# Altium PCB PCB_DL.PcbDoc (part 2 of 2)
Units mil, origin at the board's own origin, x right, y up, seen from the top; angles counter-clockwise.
Board outline 3150 x 3254.21 mil, 2 copper layers (Top Layer, Bottom Layer); 110 components, 96 nets, 420 pads, 120 vias.
Unrouted connection lines stored in the file: 79.
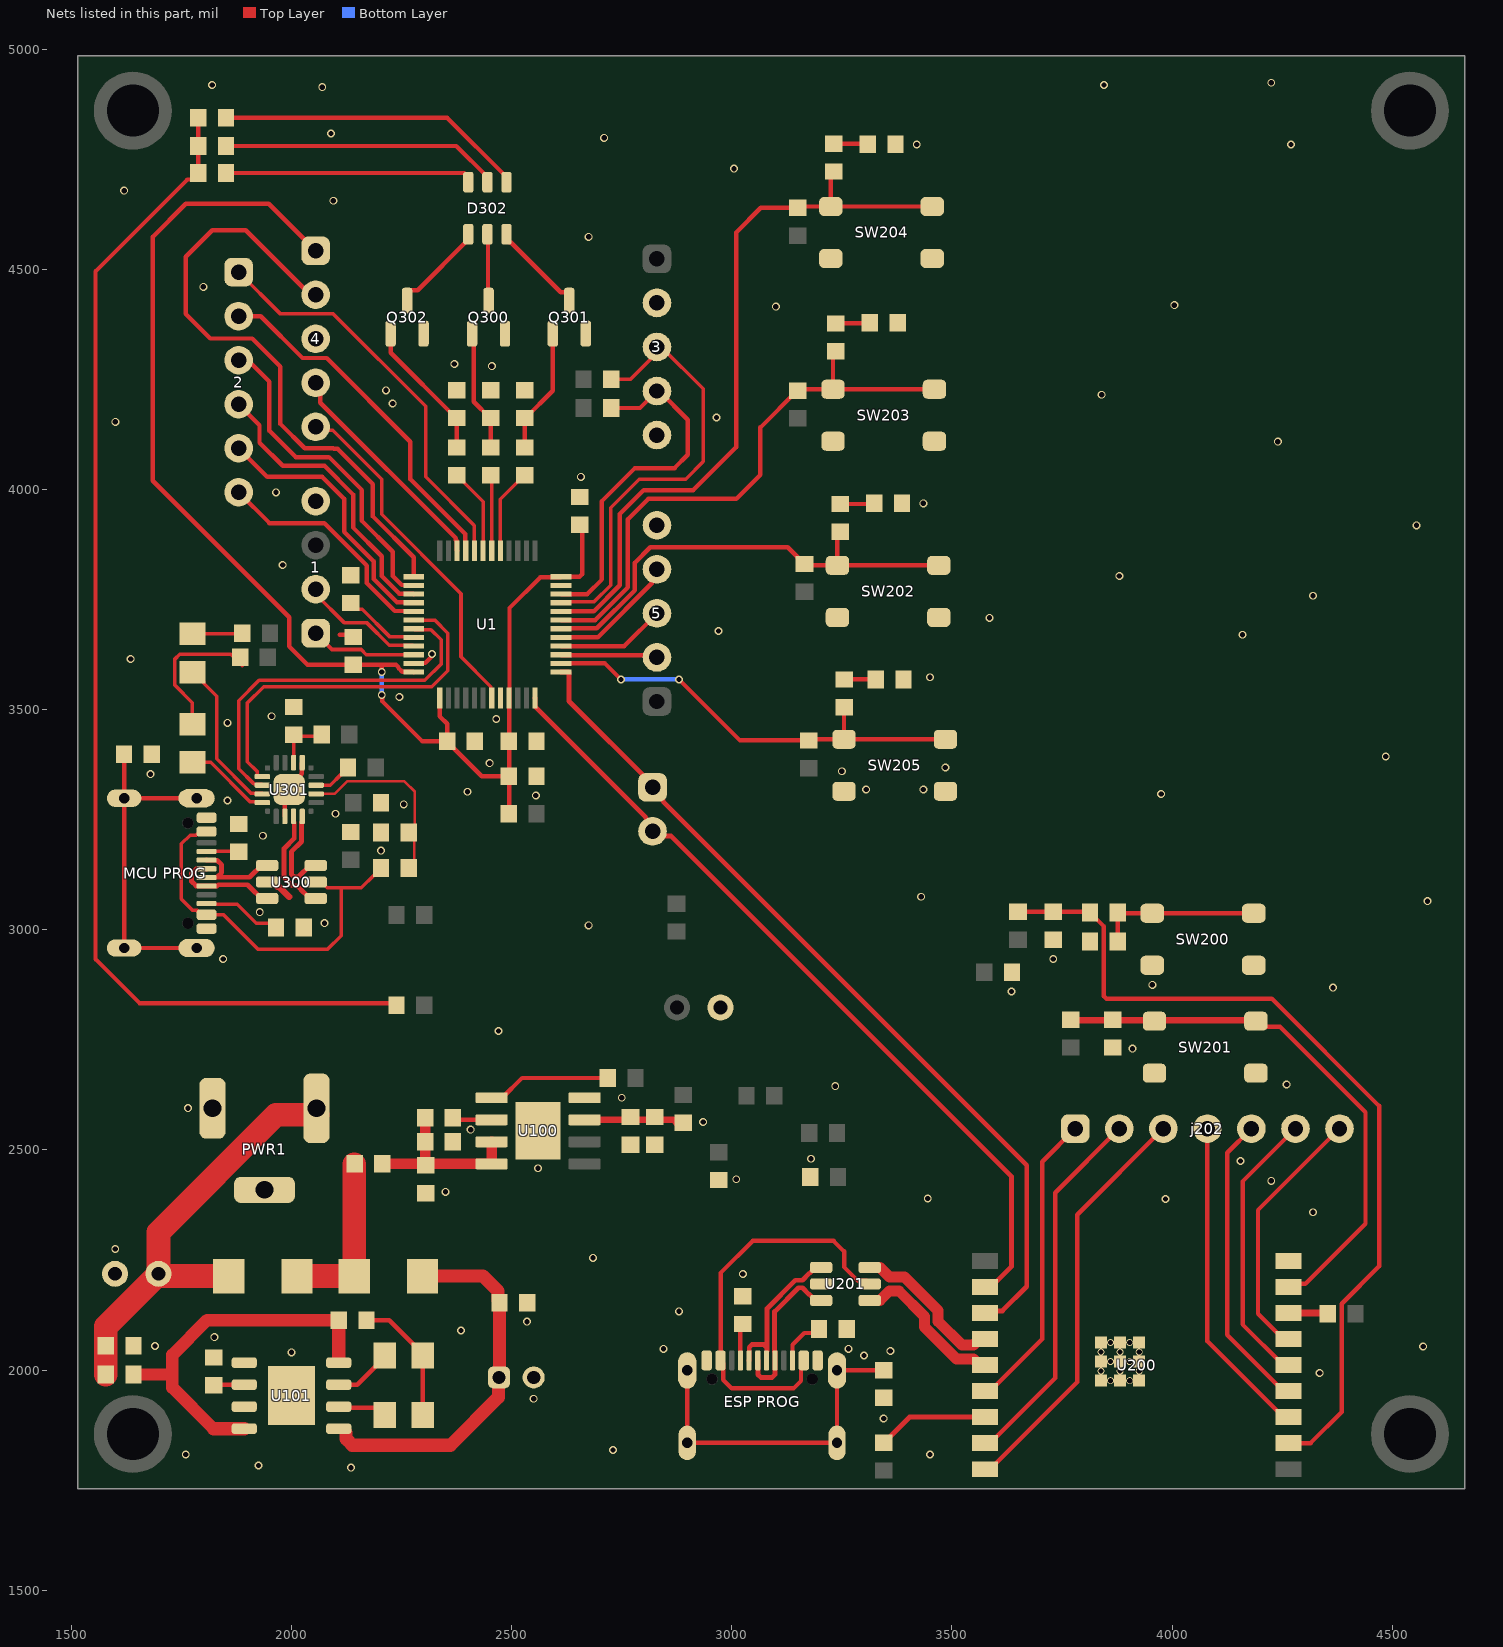
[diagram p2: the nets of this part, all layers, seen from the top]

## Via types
v1: diameter 18, hole 12, Top Layer to Bottom Layer, tented both sides, 120 vias

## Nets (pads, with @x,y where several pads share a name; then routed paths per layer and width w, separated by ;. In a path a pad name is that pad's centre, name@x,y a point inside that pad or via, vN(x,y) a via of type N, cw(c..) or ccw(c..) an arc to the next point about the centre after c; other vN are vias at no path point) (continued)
3V3_LED: FB302.2 R311.2 R312.2 R313.2 | length 2749.3
  Top Layer w10: R311.2@1788.66,4718.51 R311.2@1788.66,4728.66 ; R313.2@1788.66,4844.3 R312.2@1788.66,4779.86 R311.2@1788.66,4728.66 ; FB302.2@2238.57,2833.5 1655.07,2833.5 1555.07,2933.5 1555.07,4495.07 1763.73,4703.73 1775.16,4703.73 1788.66,4717.23 R311.2@1788.66,4728.66
3V3_MCU: 4.1 C1.1 C2.1 C3.1 C4.1 C5.1 FB1.2 U1.1 U1.9 U1.24 U1.48 | length 3133.8
  Top Layer w10: 4.1@2055,4542 1948.5,4648.5 1760.07,4648.5 1685.07,4573.5 1685.07,4019.93 1995.07,3709.93 1995.07,3643.5 2036.57,3602 C4.1@2140.07,3602 2205.07,3602 ; v1(2205.07,3533) 2206.6,3531.47 2206.6,3518.69 2296.78,3428.5 C3.1@2353.57,3428.5 2353.57,3467.7 2336.8,3484.47 U1.1@2336.8,3526.18 ; v1(2205.07,3585.5) 2205.07,3602 ; U1.48@2277.75,3585.23 2276.75,3586.23 2251.37,3586.23 2243.25,3594.36 2243.25,3596.14 2237.39,3602 2205.07,3602 ; C3.1@2353.57,3427 2432.07,3348.5 C1.1@2493.57,3348.5 ; FB1.2@2494.28,3264.21 U1.9@2494.28,3526.18 2495.28,3527.18 2495.28,3730.69 2565.36,3800.77 2611.39,3800.77 U1.24@2612.39,3801.77 2654.21,3801.77 2660.07,3807.63 2660.07,3907 C5.1@2650.07,3917
  Bottom Layer w10: v1(2205.07,3533) v1(2205.07,3585.5)
5V: C100.1 C106.1 D103.2 FB101.1 PWR1.1 | length 1000.6
  Top Layer w54: FB101.1@1578.5,1990.17 1578.5,2099.36 C100.1@1697.97,2218.82 ; D103.2@1847.71,2213.7 1697,2213.7 1697,2217.86 C100.1@1697.97,2218.82 ; PWR1.1@2059.47,2580 1965,2580 1697.97,2312.97 C100.1@1697.97,2218.82
BTN_1: C207.1 R208.1 SW202.2 U1.18 | length 1063.5
  Top Layer w10: U1.18@2612.39,3683.66 2613.39,3684.66 2693.6,3684.66 2780.07,3771.13 2780.07,3833.5 2815.07,3868.5 3127.28,3868.5 3150.07,3845.71 3150.07,3844.21 3163.57,3830.71 R208.1@3165.07,3830.71 ; R208.1@3168.22,3827.56 SW202.2@3239.91,3827.56 ; C207.1@3246.49,3904 3239.91,3897.43 SW202.2@3239.91,3827.56 ; SW202.2@3470.23,3827.56 SW202.2@3239.91,3827.56
BTN_2: C208.1 R209.1 SW203.2 U1.19 | length 1303.2
  Top Layer w10: U1.19@2612.39,3703.34 2689.66,3703.34 2764.07,3777.76 2764.07,3932.5 2810.07,3978.5 3010.07,3978.5 3065.07,4033.5 3065.07,4140.9 3148.57,4224.4 R209.1@3150.07,4224.4 ; R209.1@3153.22,4227.56 SW203.2@3229.91,4227.56 ; C208.1@3236.49,4314 3229.91,4307.43 SW203.2@3229.91,4227.56 ; SW203.2@3460.23,4227.56 SW203.2@3229.91,4227.56
BTN_3: C209.1 R210.1 SW204.2 U1.20 | length 1681.8
  Top Layer w10: U1.20@2612.39,3723.03 2686.71,3723.03 2745.81,3782.12 2745.81,3944.24 2800.07,3998.5 2912.34,3998.5 3010.07,4096.23 3010.07,4583.5 3065.97,4639.4 R210.1@3150.07,4639.4 ; R210.1@3153.22,4642.56 SW204.2@3224.91,4642.56 ; C209.1@3231.49,4722 3224.91,4715.43 SW204.2@3224.91,4642.56 ; SW204.2@3455.23,4642.56 SW204.2@3224.91,4642.56
BTN_4: C210.1 R211.1 SW205.2 U1.14 | length 1016
  Top Layer w10: U1.14@2612.39,3604.92 2711.9,3604.92 v1(2748.58,3568.24) ; v1(2880.07,3568.5) 3018.57,3430 R211.1@3175.07,3430 ; R211.1@3177.62,3432.56 SW205.2@3254.91,3432.56 ; C210.1@3255.07,3505.5 3254.91,3505.34 SW205.2@3254.91,3432.56 ; SW205.2@3485.23,3432.56 SW205.2@3254.91,3432.56
  Bottom Layer w10: v1(2748.58,3568.24) 2748.84,3568.5 v1(2880.07,3568.5)
D2_C_N: "ESP PROG.A7" "ESP PROG.B7" U201.1 | length 353.6
  Top Layer w11: 3039.4,2021.98 3039.81,2022.38 3039.81,2052.06 3046.25,2058.5 3071.93,2058.5 3078.37,2052.06 ; 3079.18,2022.38 3079.18,2042.56 3080.12,2043.5 3080.12,2139.97 3144.41,2204.26 3160.56,2204.26 3176.36,2220.06 3176.58,2220.06 3189.68,2233.16 U201.1@3202.96,2233.16
D2_C_P: "ESP PROG.A6" "ESP PROG.B6" U201.3 | length 360.1
  Top Layer w11: 3059.09,2021.98 3059.49,2021.57 3059.49,1989.94 3065.94,1983.5 3091.61,1983.5 3098.05,1989.94 3098.05,2021.57 3098.46,2021.98 3098.05,2022.38 3098.05,2041.42 3097.12,2042.36 3097.12,2132.93 3151.45,2187.26 3160.56,2187.26 3176.36,2171.47 3176.58,2171.47 3189.68,2158.36 U201.3@3202.96,2158.36
D_C_N: "MCU PROG.A7" "MCU PROG.B7" U300.1 | length 220
  Top Layer w11: 1807.23,3118.82 1807.63,3119.22 1831.02,3119.22 ; 1807.23,3158.19 1807.63,3157.78 1831.02,3157.78 1841.37,3147.44 1841.37,3129.56 1831.02,3119.22 ; U300.1@1944.95,3145.9 1931.67,3145.9 1918.56,3132.8 1918.34,3132.8 1904.77,3119.22 1831.02,3119.22
D_C_P: "MCU PROG.A6" "MCU PROG.B6" U300.3 | length 247
  Top Layer w11: 1807.23,3138.5 1806.82,3138.09 1783.43,3138.09 1773.09,3127.75 1773.09,3109.88 1783.43,3099.54 1806.82,3099.54 1807.23,3099.13 1807.63,3099.54 1831.02,3099.54 1833.71,3102.22 1900.33,3102.22 1918.34,3084.2 1918.56,3084.2 1931.67,3071.1 U300.3@1944.95,3071.1
DATA_ESP_N: U200.13 U201.6 | length 354.9
  Top Layer w25: U201.6@3313.2,2233.16 3313.49,2232.87 3336.9,2232.87 3358.5,2211.27 3392.05,2211.27 3468.33,2134.99 3468.33,2111 3522.69,2056.64 3549.23,2056.64 3563.26,2070.67 U200.13@3575.07,2070.67
DATA_ESP_P: U200.14 U201.4 | length 354.9
  Top Layer w25: U201.4@3313.2,2158.36 3313.49,2158.66 3336.89,2158.66 3358.5,2180.27 3379.21,2180.27 3437.33,2122.15 3437.33,2098.16 3509.84,2025.64 3549.23,2025.64 3563.26,2011.61 U200.14@3575.07,2011.61
DATA_MCU_N: U300.6 U301.5 | length 209.9
  Top Layer w11: U301.5@2024.6,3257.48 2024.6,3245.67 2023.25,3244.32 2023.25,3200.51 2000.07,3177.32 2000.07,3126.29 2006.51,3119.85 2015.62,3119.85 2028.58,3132.8 2028.81,3132.8 2041.91,3145.9 U300.6@2055.19,3145.9
DATA_MCU_P: U300.4 U301.4 | length 240.4
  Top Layer w11: U301.4@2004.91,3257.48 2004.91,3245.67 2006.25,3244.32 2006.25,3207.55 1983.07,3184.36 1983.07,3119.25 2002.31,3100 2012.79,3100 2028.58,3084.21 2028.79,3084.21 2041.91,3071.1 U300.4@2055.19,3071.1
ESP_BOOT: C204.1 R203.1 SW201.2 U200.8 | length 1243.9
  Top Layer w10: SW201.2@4190.23,2792.56 4202.78,2780 4245,2780 4439.12,2585.88 4439.12,2332.56 4302.71,2196.15 4271.42,2196.15 U200.8@4264.04,2188.78
  Top Layer w15: R203.1@3770.07,2795.71 3771.65,2794.13 3865.07,2794.13 3959.91,2794.13 4188.65,2794.13 SW201.2@4190.23,2792.56
GND: 1.4 3.2 3.5 4.3 5.5 "ESP PROG.A1/B12" "ESP PROG.B1/A12" "MCU PROG.A1/B12" "MCU PROG.B1/A12" C1.2 C2.2 C3.2 C4.2 C5.2 C100.2 C101.2 C102.2 C103.2 C104.2 C105.2 C106.2 C200.2 C201.2 C202.2 C203.2 C204.2 C300.2 C301.2 FB200.1 FB301.1 PWR1.2 PWR1.3 Q300.2 Q301.2 Q302.2 R1.1 R103.2 R104.1 R106.2 R212.1 R213.1 R214.1 R215.1 R216.1 R217.1 R303.1 R304.1 R307.1 R308.1 R310.1 R316.1 R317.1 SW200.1 SW201.1 SW202.1 SW203.1 SW204.1 SW205.1 U1.8 U1.23 U1.47 U100.8 U100.9 U101.1 U101.3 U101.9 U200.9 U200.19 U201.2 U300.2 U301.3 U301.12 U301.21 X101.2 | length 287.9
  Top Layer w10: U301.3@1985.23,3257.48 1985.23,3308.66 U301.21@1995.07,3318.5 1995.07,3325.38 2023.69,3354 2023.69,3378.62 U301.12@2024.6,3379.52 ; 2110.07,3670 2135.07,3670 C4.2@2140.07,3665 ; U1.47@2277.75,3604.92 2278.75,3605.92 2304.12,3605.92 2317.67,3619.48 2317.67,3624.71 v1(2319.21,3626.24)
  Top Layer w15: U300.2@1944.95,3108.5 1957.75,3108.5 1968.85,3097.39 1972.39,3097.39 1995.07,3074.71
  other v1: 2135.07,1778.5 1925.07,1783.5 1760.07,1808.5 3450.07,1808.5 2730.07,1818.5 3344.87,1890.12 2550,1935 4335.07,1993.5 3300.07,2033.5 2000.07,2040.43 3360.07,2043.5 2845.07,2048.5 3265.07,2048.5 4570.07,2053.5 1690,2055 1825,2075 2385,2090 2535,2110 2880.07,2133.5 3025.07,2218.5 2685,2255 1600,2275 4320.07,2358.5 3985.07,2388.5 3445,2390 2350,2405 4225,2430 3010.07,2433.5 2560.07,2458.5 4155,2475 3180,2480 2406.93,2546.18 2935.07,2563.5 1765,2595 2750.07,2618.5 3235,2645 4260.07,2648.5 3910,2730 2470,2770 3635,2860 4365.07,2868.5 3955,2875 1845.07,2933.5 3730.07,2933.5 2675,3010 2075,3015 1928.09,3040.01 4580,3065 3430,3075 2203.51,3179.64 1935.07,3213.5 2100.07,3263.5 2255,3285 1855.07,3293.5 2555,3305 3975.07,3308.5 2400.07,3313.5 3305.07,3318.5 3435.07,3318.5 1680.07,3353.5 3250,3360 3485.07,3368.5 2450.07,3378.5 4485.07,3393.5 1855,3470 2465.07,3478.5 1955,3485 2245.07,3528.5 3450.07,3573.5 1635,3615 4160,3670 2970.07,3678.5 3585.07,3708.5 4320.07,3758.5 3880.07,3803.5 1980.07,3828.5 4555.07,3918.5 3435.07,3968.5 1965.07,3993.5 2657.11,4028.5 4240.07,4108.5 1600.07,4153.5 2965.07,4163.5 2230,4195 3840,4215 2215,4225 2455,4280 2370,4285 3100,4415 4005.07,4418.5 1800,4460 2675.07,4573.5 2095.07,4655.51 1620.07,4678.5 3005.07,4728.5 3420.07,4783.5 4270.07,4783.5 2710.07,4798.5 2090.07,4808.5 2070.07,4913.5 1820.07,4918.5 3845.07,4918.5 4225.07,4923.5
I/O_0: j202.3 U200.18 | length 947.8
  Top Layer w10: U200.18@3575.07,1775.39 3586.88,1775.39 3784.57,1973.08 3784.57,2353 j202.3@3980.07,2548.5
I/O_1: j202.2 U200.17 | length 847.3
  Top Layer w10: U200.17@3575.07,1834.44 3586.88,1834.44 3734.57,1982.14 3734.57,2403 j202.2@3880.07,2548.5
I/O_3: j202.1 U200.15 | length 687.8
  Top Layer w10: U200.15@3575.07,1952.56 3586.88,1952.56 3705,2070.68 3705,2473.43 j202.1@3780.07,2548.5
I/O_4: j202.4 U200.3 | length 738.1
  Top Layer w10: j202.4@4080.07,2548.5 4080.07,2065.67 4252.23,1893.5 U200.3@4264.04,1893.5
I/O_5: j202.5 U200.4 | length 683.3
  Top Layer w10: j202.5@4180.07,2548.5 4125,2493.43 4125,2080 4239.52,1965.48 4239.52,1965.27 4252.23,1952.56 U200.4@4264.04,1952.56
I/O_6: j202.6 U200.5 | length 636.6
  Top Layer w10: U200.5@4264.04,2011.61 4252.23,2011.61 4160,2103.84 4160,2428.43 j202.6@4280.07,2548.5
I/O_7: j202.7 U200.6 | length 590
  Top Layer w10: U200.6@4264.04,2070.67 4252.23,2070.67 4195.07,2127.83 4195.07,2363.5 j202.7@4380.07,2548.5
LB: D302.1 Q302.3 | length 218.6
  Top Layer w10: Q302.3@2262.67,4428.5 2262.67,4445.73 2269.41,4452.47 2286.6,4452.47 2401.76,4567.63 D302.1@2401.76,4579.44
LED1_B: R315.1 U1.31 | length 197
  Top Layer w8: R315.1@2375.07,4032 2376.57,4032 2391.07,4017.5 2391.07,4016 2435.23,3971.84 U1.31@2435.23,3860.82
LED1_G: R309.1 U1.30 | length 171.2
  Top Layer w8: U1.30@2454.91,3860.82 2454.91,4031.84 R309.1@2455.07,4032
LED1_R: R314.1 U1.29 | length 195
  Top Layer w8: U1.29@2474.6,3860.82 2474.6,3978.03 2528.57,4032 R314.1@2530.07,4032
LG: D302.2 Q300.3 | length 152
  Top Layer w10: D302.2@2445.07,4579.44 2446.37,4578.15 2446.37,4429.8 Q300.3@2447.67,4428.5
LR: D302.3 Q301.3 | length 219.3
  Top Layer w10: D302.3@2488.38,4579.44 2488.38,4568.12 2495.12,4561.38 2498.17,4561.38 2611.51,4448.05 2624.31,4448.05 2631.05,4441.3 Q301.3@2631.05,4428.5
NetC101_1: C101.1 C102.1 FB100.2 R101.2 U100.3 U100.4 | length 407.9
  Top Layer w10: C101.1@2303.57,2470 C101.1@2305.07,2468.5 ; C102.1@2303.57,2517 C102.1@2303.57,2518.5 ; 2366.57,2468.5 2370.07,2465 2373.57,2468.5
  Top Layer w24: FB100.2@2206.57,2468.5 2305.07,2468.5 2366.57,2468.5 ; C101.1@2303.57,2470 C102.1@2303.57,2518.5 R101.2@2303.57,2573.5 ; 2373.57,2468.5 U100.4@2454.46,2468.5 U100.3@2454.46,2518.5
NetC200_1: C200.1 R200.2 R201.2 U200.2 | length 1975.6
  Top Layer w10: R200.2@3650.07,3040.71 C200.1@3730.07,3040.71 3812.07,3040.71 R201.2@3813.57,3039.21 3845.07,3007.71 3845.07,2849.36 3850.93,2843.5 4226.5,2843.5 4470,2600 4470,2235.99 4385,2150.99 4385,1905 4314.44,1834.44 U200.2@4264.04,1834.44
NetC201_1: C201.1 R201.1 SW200.2 | length 375.1
  Top Layer w10: C201.1@3876.57,2973.5 R201.1@3876.57,3039.21 3878.22,3037.56 SW200.2@3954.91,3037.56 SW200.2@4185.23,3037.56
NetC207_2: C207.2 R214.2 | length 77.7
  Top Layer w10: C207.2@3246.49,3967 3322.07,3967 R214.2@3323.57,3968.5
NetC208_2: C208.2 R215.2 | length 77.7
  Top Layer w10: C208.2@3236.49,4377 3312.07,4377 R215.2@3313.57,4378.5
NetC209_2: C209.2 R216.2 | length 77.7
  Top Layer w10: C209.2@3231.49,4785 3307.07,4785 R216.2@3308.57,4783.5
NetC210_2: C210.2 R217.2 | length 72
  Top Layer w10: C210.2@3255.07,3568.5 R217.2@3327.07,3568.5
NetD101_1: D101.1 D102.1 R105.2 | length 298.5
  Top Layer w10: R105.2@2170.35,2113.5 2222.31,2113.5 2298.38,2037.44 D102.1@2298.38,2033.5 D101.1@2298.38,1898.5
NetD101_2: D101.2 U101.6 | length 112.1
  Top Layer w10: U101.6@2107.36,1917.01 2109.62,1914.73 2195.53,1914.73 D101.2@2211.76,1898.5
NetD102_2: D102.2 U101.7 | length 134.3
  Top Layer w10: U101.7@2107.36,1967.01 2149.2,1967 2211.76,2029.56 D102.2@2211.76,2033.5
NetD300_1: D300.1 R300.1 | length 334.2
  Top Layer w8: D300.1@1775.07,3466.81 1775.07,3515.93 1735.54,3555.46 1735.54,3614.93 1746.43,3625.81 1862.75,3625.81 1873.32,3615.25 R300.1@1888.57,3600 ; R300.1@1872.57,3614.5 R300.1@1874.07,3614.5
NetD300_2: D300.2 U301.20 | length 196.8
  Top Layer w8: D300.2@1775.07,3380.19 1816.6,3380.19 1905.91,3290.88 1932.14,3290.88 U301.20@1934.04,3288.97
NetD301_1: D301.1 R301.1 | length 115.7
  Top Layer w8: D301.1@1775.07,3671.81 1886.88,3671.81 R301.1@1888.57,3673.5 R301.1@1888.57,3672
NetD301_2: D301.2 U301.19 | length 358.8
  Top Layer w8: D301.2@1775.07,3585.19 1779.01,3585.19 1800.6,3563.6 1800.6,3559.67 1830.07,3530.19 1830.07,3388.5 1908.01,3310.56 1932.14,3310.56 U301.19@1934.04,3308.66
NetD302_4: D302.4 R313.1 | length 704.4
  Top Layer w10: R313.1@1851.66,4844.3 2353.44,4844.3 2488.38,4709.37 D302.4@2488.38,4697.56
NetD302_5: D302.5 R312.1 | length 634.4
  Top Layer w10: R312.1@1851.66,4779.86 2374.58,4779.86 2445.07,4709.37 D302.5@2445.07,4697.56
NetD302_6: D302.6 R311.1 | length 565.4
  Top Layer w10: R311.1@1851.66,4718.51 2392.12,4718.51 2401.76,4708.88 D302.6@2401.76,4697.56
"NetESP PROG_0": "ESP PROG.0" FB200.2 | length 775.6
  Top Layer w10: 2898.85,1999.34 2898.85,1834.77 3239.01,1834.77 3239.01,1999.34 3344.41,1999.34 FB200.2@3345.07,2000
"NetESP PROG_A5": "ESP PROG.A5" R213.2 | length 91.8
  Top Layer w10: R213.2@3015.7,2108.63 3023.18,2108.63 R213.2@3023.81,2108 ; R213.2@3018.81,2105 3018.81,2022.88 3019.72,2021.98
"NetESP PROG_B5": "ESP PROG.B5" R212.2 | length 104.8
  Top Layer w10: 3137.83,2021.98 3137.83,2057.76 3164.43,2084.36 3182.93,2084.36 R212.2@3192.07,2093.5
NetFB101_2: FB101.2 R105.1 U101.4 U101.8 | length 867
  Top Layer w28: FB101.2@1641.5,1990.17 1729.61,1990.17 ; 1823,1867 1729.61,1960.39 1729.61,1990.17 ; R105.1@2107.35,2113.5 1808.5,2113.5 1729.61,2034.61 1729.61,1990.17
  Top Layer w30: 1823,1867 U101.4@1892.8,1867.01 ; U101.8@2107.35,2021.11 R105.1@2107.35,2113.5
NetFB301_2: "MCU PROG.0" FB301.2 | length 769.2
  Top Layer w10: FB301.2@1620.02,3398.66 1620.02,3298.74 ; 1784.59,2958.58 1620.02,2958.58 1620.02,3298.74 ; 1784.59,3298.74 1620.02,3298.74
"NetMCU PROG_A5": "MCU PROG.A5" R304.2 | length 75.9
  Top Layer w8: 1809.13,3179.78 1807.23,3177.87 1879.2,3177.87 R304.2@1880.07,3177
"NetMCU PROG_B5": "MCU PROG.B5" R303.2 | length 180.4
  Top Layer w8: 1807.23,3059.76 1809.13,3057.85 1877.15,3057.85 1920,3015 1955.33,3015 R303.2@1965.08,3005.25
NetQ300_1: Q300.1 R309.2 R310.2 | length 277.1
  Top Layer w10: Q300.1@2410.27,4353.7 2414.04,4349.92 2414.04,4199.02 2451.07,4162 R310.2@2452.57,4162 R309.2@2452.57,4095
NetQ301_1: Q301.1 R314.2 R316.2 | length 285.9
  Top Layer w10: R314.2@2530.07,4095 R316.2@2530.07,4162 2531.57,4162 2593.65,4224.08 Q301.1@2593.65,4353.7
NetQ302_1: Q302.1 R315.2 R317.2 | length 321.6
  Top Layer w10: Q302.1@2225.27,4353.7 2225.27,4310.3 2373.57,4162 R317.2@2375.07,4162 R315.2@2375.07,4095
NetR1_2: R1.2 U1.44 | length 175
  Top Layer w8: R1.2@2135.07,3742 2149.05,3728.01 2160.55,3728.01 2222.6,3665.97 2275.75,3665.97 U1.44@2277.75,3663.97
NetR100_2: R100.2 U100.1 | length 282.7
  Top Layer w10: U100.1@2454.46,2618.5 2478.77,2618.5 2523.77,2663.5 R100.2@2718.57,2663.5
NetR101_1: R101.1 U100.2 | length 90
  Top Layer w10: R101.1@2366.57,2573.5 2371.57,2568.5 U100.2@2454.46,2568.5
NetR102_2: R102.2 R103.1 R104.2 U100.7 | length 224.1
  Top Layer w15: U100.7@2667.43,2566.75 U100.7@2665.68,2568.5 2770.07,2568.5 2818.32,2568.5 2867.07,2568.5 2878.57,2557 R102.2@2880.07,2557 ; R103.1@2818.32,2566.75 R103.1@2820.07,2565
NetR106_1: R106.1 U101.2 | length 72.7
  Top Layer w10: R106.1@1820.07,1967 U101.2@1892.8,1967.01
NetR204_1: R204.1 U200.7 | length 91.1
  Top Layer w15: U200.7@4264.04,2129.72 4275.86,2129.72 4276,2129.86 4354.93,2129.86 R204.1@4355.07,2130
NetR205_2: R205.2 U200.16 | length 268.2
  Top Layer w11: R205.2@3345.07,1835 3353.57,1843.5 3403.57,1893.5 U200.16@3565.23,1893.5
  Top Layer w15: R205.2@3345.07,1835 R205.2@3353.57,1843.5 ; U200.16@3563.26,1893.5 U200.16@3575.07,1893.5
NetR302_2: R302.2 U301.9 | length 90
  Top Layer w8: U301.9@2056.09,3328.34 2088.41,3328.34 2112.57,3352.5 2114.07,3352.5 2128.57,3367 R302.2@2128.57,3368.5
PA11: 2.1 U1.32 | length 924.8
  Top Layer w8: 2.1@1880.07,4493.5 1975.07,4398.5 2095.07,4398.5 2305.07,4188.5 2305.07,4028.5 2415.54,3918.03 U1.32@2415.54,3860.82
PA12: 2.2 U1.33 | length 807.8
  Top Layer w10: 2.2@1880.07,4393.5 1930.07,4393.5 2025.07,4298.5 2080.07,4298.5 2270.07,4108.5 2270.07,4023.5 2394.86,3898.71 2394.86,3861.82 U1.33@2395.86,3860.82
PA15: 2.3 U1.38 | length 747.8
  Top Layer w10: 2.3@1880.07,4293.5 1890.59,4282.98 1911.61,4282.98 1950.07,4244.52 1950.07,4133.5 2010.07,4073.5 2085.07,4073.5 2160.07,3998.5 2160.07,3928.5 2230.07,3858.5 2230.07,3803.5 2250.49,3783.08 2276.75,3783.08 U1.38@2277.75,3782.08
PB3: 2.4 U1.39 | length 670
  Top Layer w10: 2.4@1880.07,4193.5 1927.57,4146 1927.57,4106 1980.07,4053.5 2075.07,4053.5 2140.07,3988.5 2140.07,3913.5 2205.07,3848.5 2205.07,3803.5 2245.17,3763.4 2276.75,3763.4 U1.39@2277.75,3762.4
PB4: 2.5 U1.40 | length 610.3
  Top Layer w10: 2.5@1880.07,4093.5 1945.07,4028.5 2070.07,4028.5 2120.07,3978.5 2120.07,3903.5 2187.07,3836.5 2187.07,3796.5 2239.86,3743.71 2276.75,3743.71 U1.40@2277.75,3742.71
PB5: 2.6 U1.41 | length 532.9
  Top Layer w10: 2.6@1880.07,3993.5 1950.07,3923.5 2074.59,3923.5 2171.07,3827.02 2171.07,3787.5 2234.54,3724.03 2276.75,3724.03 U1.41@2277.75,3723.03
R\S\T\: 4.5 U1.7 | length 803
  Top Layer w8: 4.5@2048.79,4134.32 2094.25,4134.32 2205.07,4023.5 2205.07,3943.5 2385.07,3763.5 2385.07,3619.98 2452.91,3552.13 2452.91,3528.18 U1.7@2454.91,3526.18
RX_ESP: j203.1 U1.13 U200.12 | length 1963.5
  Top Layer w11: U1.13@2612.39,3585.23 2629.89,3585.23 2630.39,3584.73 2630.39,3519 2820.07,3329.32 2820.07,3317.68 2844.19,3293.56 2844.19,3290.81 3670,2465 3670,2190 3614.65,2134.65 3580,2134.65 U200.12@3575.07,2129.72
RX_USB: U1.43 U301.18 | length 846
  Top Layer w8: U301.18@1934.04,3328.34 1932.14,3330.25 1917.52,3330.25 1915.64,3332.12 1913.92,3332.12 1880.07,3365.97 1880.07,3520.07 1926.5,3566.5 2303.07,3566.5 2340.07,3603.5 2340.07,3658.5 2316.91,3681.66 2279.75,3681.66 U1.43@2277.75,3683.66
SCL_IMU: 3.3 R5.1 U1.21 | length 999.8
  Top Layer w8: U1.21@2612.39,3742.71 2614.39,3744.71 2687.19,3744.71 2725.07,3782.6 2725.07,3958.5 2790.07,4023.5 2895.07,4023.5 2935.07,4063.5 2935.07,4228.5 3.3@2840.07,4323.5 ; R5.1@2726.5,4250 2770,4250 2830.07,4310.07 3.3@2830.07,4323.5
SCL_OLED: 1.2 U1.45 | length 282.7
  Top Layer w8: 1.2@2055.07,3773.5 2055.07,3762.36 2120.63,3696.8 2171.77,3696.8 2222.28,3646.29 2275.75,3646.29 U1.45@2277.75,3644.29
SDA_IMU: 3.4 R4.1 U1.22 | length 819.3
  Top Layer w10: U1.22@2612.39,3762.4 2671.89,3762.4 2705.07,3795.57 2705.07,3973.5 2780.07,4048.5 2870.07,4048.5 2900.07,4078.5 2900.07,4158.5 2835.07,4223.5 3.4@2830.07,4223.5 2791.57,4185 R4.1@2726.5,4185
SDA_OLED: 1.1 U1.46 | length 242.9
  Top Layer w8: 1.1@2055.07,3673.5 2092.07,3636.5 2158.21,3636.5 2170.11,3624.6 U1.46@2277.75,3624.6
SPI1_MISO: 5.3 U1.16 | length 248.4
  Top Layer w10: U1.16@2612.39,3644.29 2755.86,3644.29 5.3@2830.07,3718.5
SPI1_MOSI: 5.4 U1.17 | length 293.4
  Top Layer w10: U1.17@2612.39,3663.97 2695.54,3663.97 2819.54,3787.98 2819.54,3807.98 5.4@2830.07,3818.5
SPI1_SCK: 5.2 U1.15 | length 220.2
  Top Layer w10: U1.15@2612.39,3624.6 2613.39,3623.6 2824.97,3623.6 5.2@2830.07,3618.5
SYS_SWCLK: 4.2 U1.37 | length 1420.3
  Top Layer w10: 4.2@2055,4442 2043,4442 1896.5,4588.5 1820.07,4588.5 1760.07,4528.5 1760.07,4398.5 1815.78,4342.78 1910.78,4342.78 1975.07,4278.5 1975.07,4148.5 2030.07,4093.5 2095.07,4093.5 2096.56,4092.01 2105,4092.01 2185.07,4011.94 2185.07,3938.5 2277.75,3845.82 U1.37@2277.75,3801.77
SYS_SWDIO: 4.4 U1.34 | length 514.2
  Top Layer w10: 4.4@2055,4242 2065.52,4231.48 2065.52,4196.84 2373.49,3888.88 2373.49,3885.18 2375.17,3883.5 2375.17,3861.82 U1.34@2376.17,3860.82
TX_ESP: j203.2 U1.12 U200.11 | length 1822.2
  Top Layer w11: U1.12@2553.34,3526.18 2553.84,3525.68 2553.84,3506.31 2804.71,3255.44 2804.71,3253.47 2820.07,3238.11 j203.2@2820.07,3223.5 ; j203.2@2830.4,3213.17 2861.83,3213.17 3635.07,2439.93 3635.07,2235.07 3600.99,2200.99 3587.29,2200.99 U200.11@3575.07,2188.78
TX_USB: U1.42 U301.17 | length 846.8
  Top Layer w8: U301.17@1934.04,3348.03 1924.52,3348.03 1922.61,3349.93 1922.61,3359.46 1900.07,3382 1900.07,3515.07 1937,3552 2318.57,3552 2355.07,3588.5 2355.07,3673.5 2325.23,3703.34 U1.42@2277.75,3703.34
USB_DETECT: R306.1 R307.2 U301.8 | length 434.4
  Top Layer w6: U301.8@2056.09,3308.66 2098.05,3308.66 2126.68,3337.29 2256.28,3337.29 2280.07,3313.5 2280.07,3234.45 R307.2@2266.57,3220.95 2278.53,3208.99 2278.53,3152.21 R306.1@2266.57,3140.25
VBAT: C105.1 D100.2 U101.5 X101.1 | length 858.3
  Top Layer w30: U101.5@2123.9,1858.5 2123.9,1843.92 2127.46,1840.36 2138.14,1829.67 2361.24,1829.67 2470.04,1938.47 2470.04,1982.21 X101.1@2471.33,1983.5 ; D100.2@2277.43,2213.5 2435.07,2213.5 2469.18,2179.39 2469.18,2158.02 2472.56,2154.64 C105.1@2473.45,2154.64 ; X101.1@2472.68,1984.85 C105.1@2472.68,2153.02
VBUS: "MCU PROG.A4/B9" "MCU PROG.B4/A9" R306.2 U300.5 | length 898.8
  Top Layer w8: 1807.23,3223.15 1800.59,3216.51 1785.41,3216.51 1783.9,3215 1770,3215 1750,3195 1750,3070 1776.15,3043.85 1785.68,3043.85 1795.37,3034.17 1845.83,3034.17 1923.71,2956.29 2082.86,2956.29 2113.12,2986.56 2113.12,3095.44 ; U300.5@2055.19,3108.51 2068.4,3108.51 2081.46,3095.44 2113.12,3095.44 ; R306.2@2203.57,3140.25 2203.57,3138.75 2189.07,3124.25 2187.57,3124.25 2158.76,3095.44 2113.12,3095.44
VBUS2: "ESP PROG.A4/B9" "ESP PROG.B4/A9" U201.5 | length 919.5
  Top Layer w10: 2971.73,2024.69 2980.7,2015.73 2980.7,1977.87 3000.07,1958.5 3140.07,1958.5 3157.17,1975.6 3157.17,2015.73 3163.42,2021.98 ; 2974.62,2022.16 2974.62,2220.61 3047.51,2293.5 3231.21,2293.5 3255.07,2269.64 3255.07,2234.21 3286.57,2202.7 3306.27,2202.7 U201.5@3313.2,2195.77
VLDO: D100.1 D103.1 FB100.1 | length 364.4
  Top Layer w54: D103.1@2012.43,2213.5 D100.1@2122.71,2213.5 ; D100.1@2142.71,2213.5 FB100.1@2142.71,2467.64
WAKE_UP: R305.1 R308.2 U301.13 | length 131.6
  Top Layer w8: U301.13@2004.91,3379.52 2004.91,3435.16 2000.07,3440 2067.07,3440 R305.1@2068.57,3438.5
pads on no net: "ESP PROG." "ESP PROG.A8" "ESP PROG.B8" "MCU PROG." "MCU PROG.A8" "MCU PROG.B8" U1.2 U1.3 U1.4 U1.5 U1.6 U1.10 U1.11 U1.25 U1.26 U1.27 U1.28 U1.35 U1.36 U100.5 U200.10 U301.1 U301.2 U301.10 U301.11 U301.14 U301.15 U301.16

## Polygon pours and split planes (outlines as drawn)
GND on Top Layer "GND_L01_P019" (solid, pour order 19): 1930,4370 2010,4290 2010,4145 2004.79,4139.79 1998.16,4139.79 1998.16,4143.23 1985.53,4155.87 1986.8,4157.14 1986.8,4286.49 1984.26,4286.49 1915.17,4355.58 1911.48,4355.58 1927.88,4371.98
GND on Top Layer "GND_L01_P017" (solid, pour order 17): 2110.02,4244.98 2255,4100 2255,4025 2170.12,4112.64 2083.36,4196.64
GND on Top Layer "GND_L01_P016" (solid, pour order 16): 2038.29,3242.87 2038.4,3242.77 2066.77,3242.77 2066.77,3207.26 2105.3,3168.72 2105.3,3133.21 2110.58,3127.93 2130.76,3127.93 2148.46,3110.23 2142.62,3104.39 2095.53,3104.39 2095.36,3104.21 2091.64,3107.93 2091.64,3164.57 2086.86,3169.35 2031.6,3169.35 2021.01,3143.25 2023.03,3135.43 2016.43,3131.97 2008.33,3133.21 2010.39,3169 2037.35,3195.96 2036.9,3241.48 2036.03,3245.14 2038.21,3242.76
GND on Top Layer "GND_L01_P015" (solid, pour order 15): 2212.57,4022.94 2216.16,4022.94 2221.61,4028.39 2290.91,3956.67 2354.07,3891.31 2322.04,3892.67 2320.99,3847.98 2216.16,3951.22 2216.16,4023.56
GND on Top Layer "GND_L01_P013" (solid, pour order 13): 1739.95,3290.23 1735.96,3286.05 1755.02,3266.96 1742.26,3250.69 1742.26,3235.17 1758.2,3219.23 1758.2,3218.87 1757.96,3218.87 1737.9,3198.81 1737.9,3052.5 1737.55,3052.15 1753.79,3035.91 1738.6,3020.72 1738.6,3000.53 1745.17,3000.53 1754.26,2991.44 1735.3,2972.49 1669.31,2972.49 1651.34,2990.46 1635,2990.46 1635,3266.96 1660.2,3266.96 1660.2,3277.29 1670,3284.9 1676.15,3284.9 1737.08,3284.9 1737.45,3284.9
GND on Top Layer "GND_L01_P012" (solid, pour order 12): 2905.82,1952.69 2910,1948.71 2930.83,1969.53 2945.36,1955 2960.88,1955 2976.82,1970.94 2977.17,1970.94 2977.17,1967.83 2995,1945.69 3070.32,1945.69 3139.29,1945.69 3145,1945.69 3159.65,1960.35 3163.02,1969.65 3181.32,1951.35 3195.52,1951.35 3195.52,1957.92 3206.19,1968.59 3223.56,1951.23 3223.56,1878.16 3209.08,1863.68 3209.08,1850 2929.09,1850 2929.09,1876.11 2918.23,1876.11 2917.36,1881.43 2915.02,1885.02 2911.15,1888.89 2911.15,1949.82 2911.15,1950.19
GND on Top Layer "GND_L01_P010" (solid, pour order 10): 3141.74,3385 3141.74,3343.26 3148.24,3336.76 3163.12,3336.76 3163.12,3296.88 3210,3250 3305,3250 3305,2865.09 3298.17,2858.26 3001.89,3154.55 3014.46,3167.12 3014.46,3181.53 3003.75,3192.24 3008.8,3197.29 3008.8,3370 3003.31,3370 2988.31,3385
GND on Top Layer "GND_L01_P006" (solid, pour order 6): 2312.78,3790 2345,3790 2375,3760 2375,3675 2370,3675 2330,3715 2312.78,3717.73
GND on Top Layer "GND_TOP" (solid, remove dead copper, pour order 3): 1515,1730.39 4665,1730.39 4665,4984.61 1515,4984.61
GND on Bottom Layer "GND_BOT" (solid, remove dead copper, pour order 4): 1515,1730.39 4665,1730.39 4665,4984.61 1515,4984.61

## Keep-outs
Keep-Out Layer:
  the board outline again, w6

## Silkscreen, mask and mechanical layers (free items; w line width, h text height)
Top Overlay:
  drawing of 143 lines, arcs and shapes, not listed
  text "JJCR" at 2590,4870 h45
  text "3V3" at 2110.07,4533.5 h30
  text "3V3" at 2890.07,4498.5 h30
  text "PA11" at 1700.07,4483.5 h30
  text "SWCLK" at 2110.07,4423.5 h25
  text "GND" at 2890.07,4403.5 h30
  text "PA12" at 1700.07,4373.5 h30
  text "GND" at 2115.26,4312.72 h25
  text "SCL_S" at 2885.07,4303.5 h30
  text "PA15" at 1700.07,4283.5 h30
  text "SWDIO" at 2110.07,4223.5 h25
  text "SDA_S" at 2885.07,4203.5 h30
  text "PB3" at 1700.07,4178.5 h30
  text "R\S\T" at 2115.07,4118.5 h25
  text "GND" at 2890.07,4098.5 h25
  text "PB4" at 1700.07,4078.5 h30
  text "PB5" at 1700.07,3978.5 h30
  text "GND" at 2120.07,3958.5 h28
  text "GND" at 2890.07,3898.5 h30
  text "3V3" at 2115.07,3858.5 h28
  text "MOSI" at 2890.07,3798.5 h30
  text "SCL D" at 1850.07,3763.5 h30
  text "SDA D" at 1850.07,3708.5 h30
  text "MISO" at 2890.07,3698.5 h30
  text "SCK" at 2890.07,3593.5 h30
  text "3V3" at 2885,3490 h30
  text "RX" at 2880,3305 h30
  text "TX" at 2880.07,3198.5 h30
  text "INPUT / 5V" at 1535,2795 h35
  text "IO3" at 3735.07,2453.5 h30
  text "IO1" at 3845.07,2453.5 h30
  text "IO0" at 3940.07,2453.5 h30
  text "IO4" at 4040.07,2453.5 h30
  text "IO5" at 4140.07,2453.5 h30
  text "IO6" at 4245.07,2453.5 h30
  text "IO7" at 4350.07,2453.5 h30
  text "BAT / 4.2V" at 2645.07,1868.5 h35
Board Shape:
  the board outline again, w6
